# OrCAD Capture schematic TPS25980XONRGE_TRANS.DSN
size E; title: TPS25980XONRGE: 2.7- 24V, 8A, 3mOhm Smart eFuse With; rev: 1.0; note: Datasheet: NA     EVM: NA; note: Adjustable Transient Fault Management
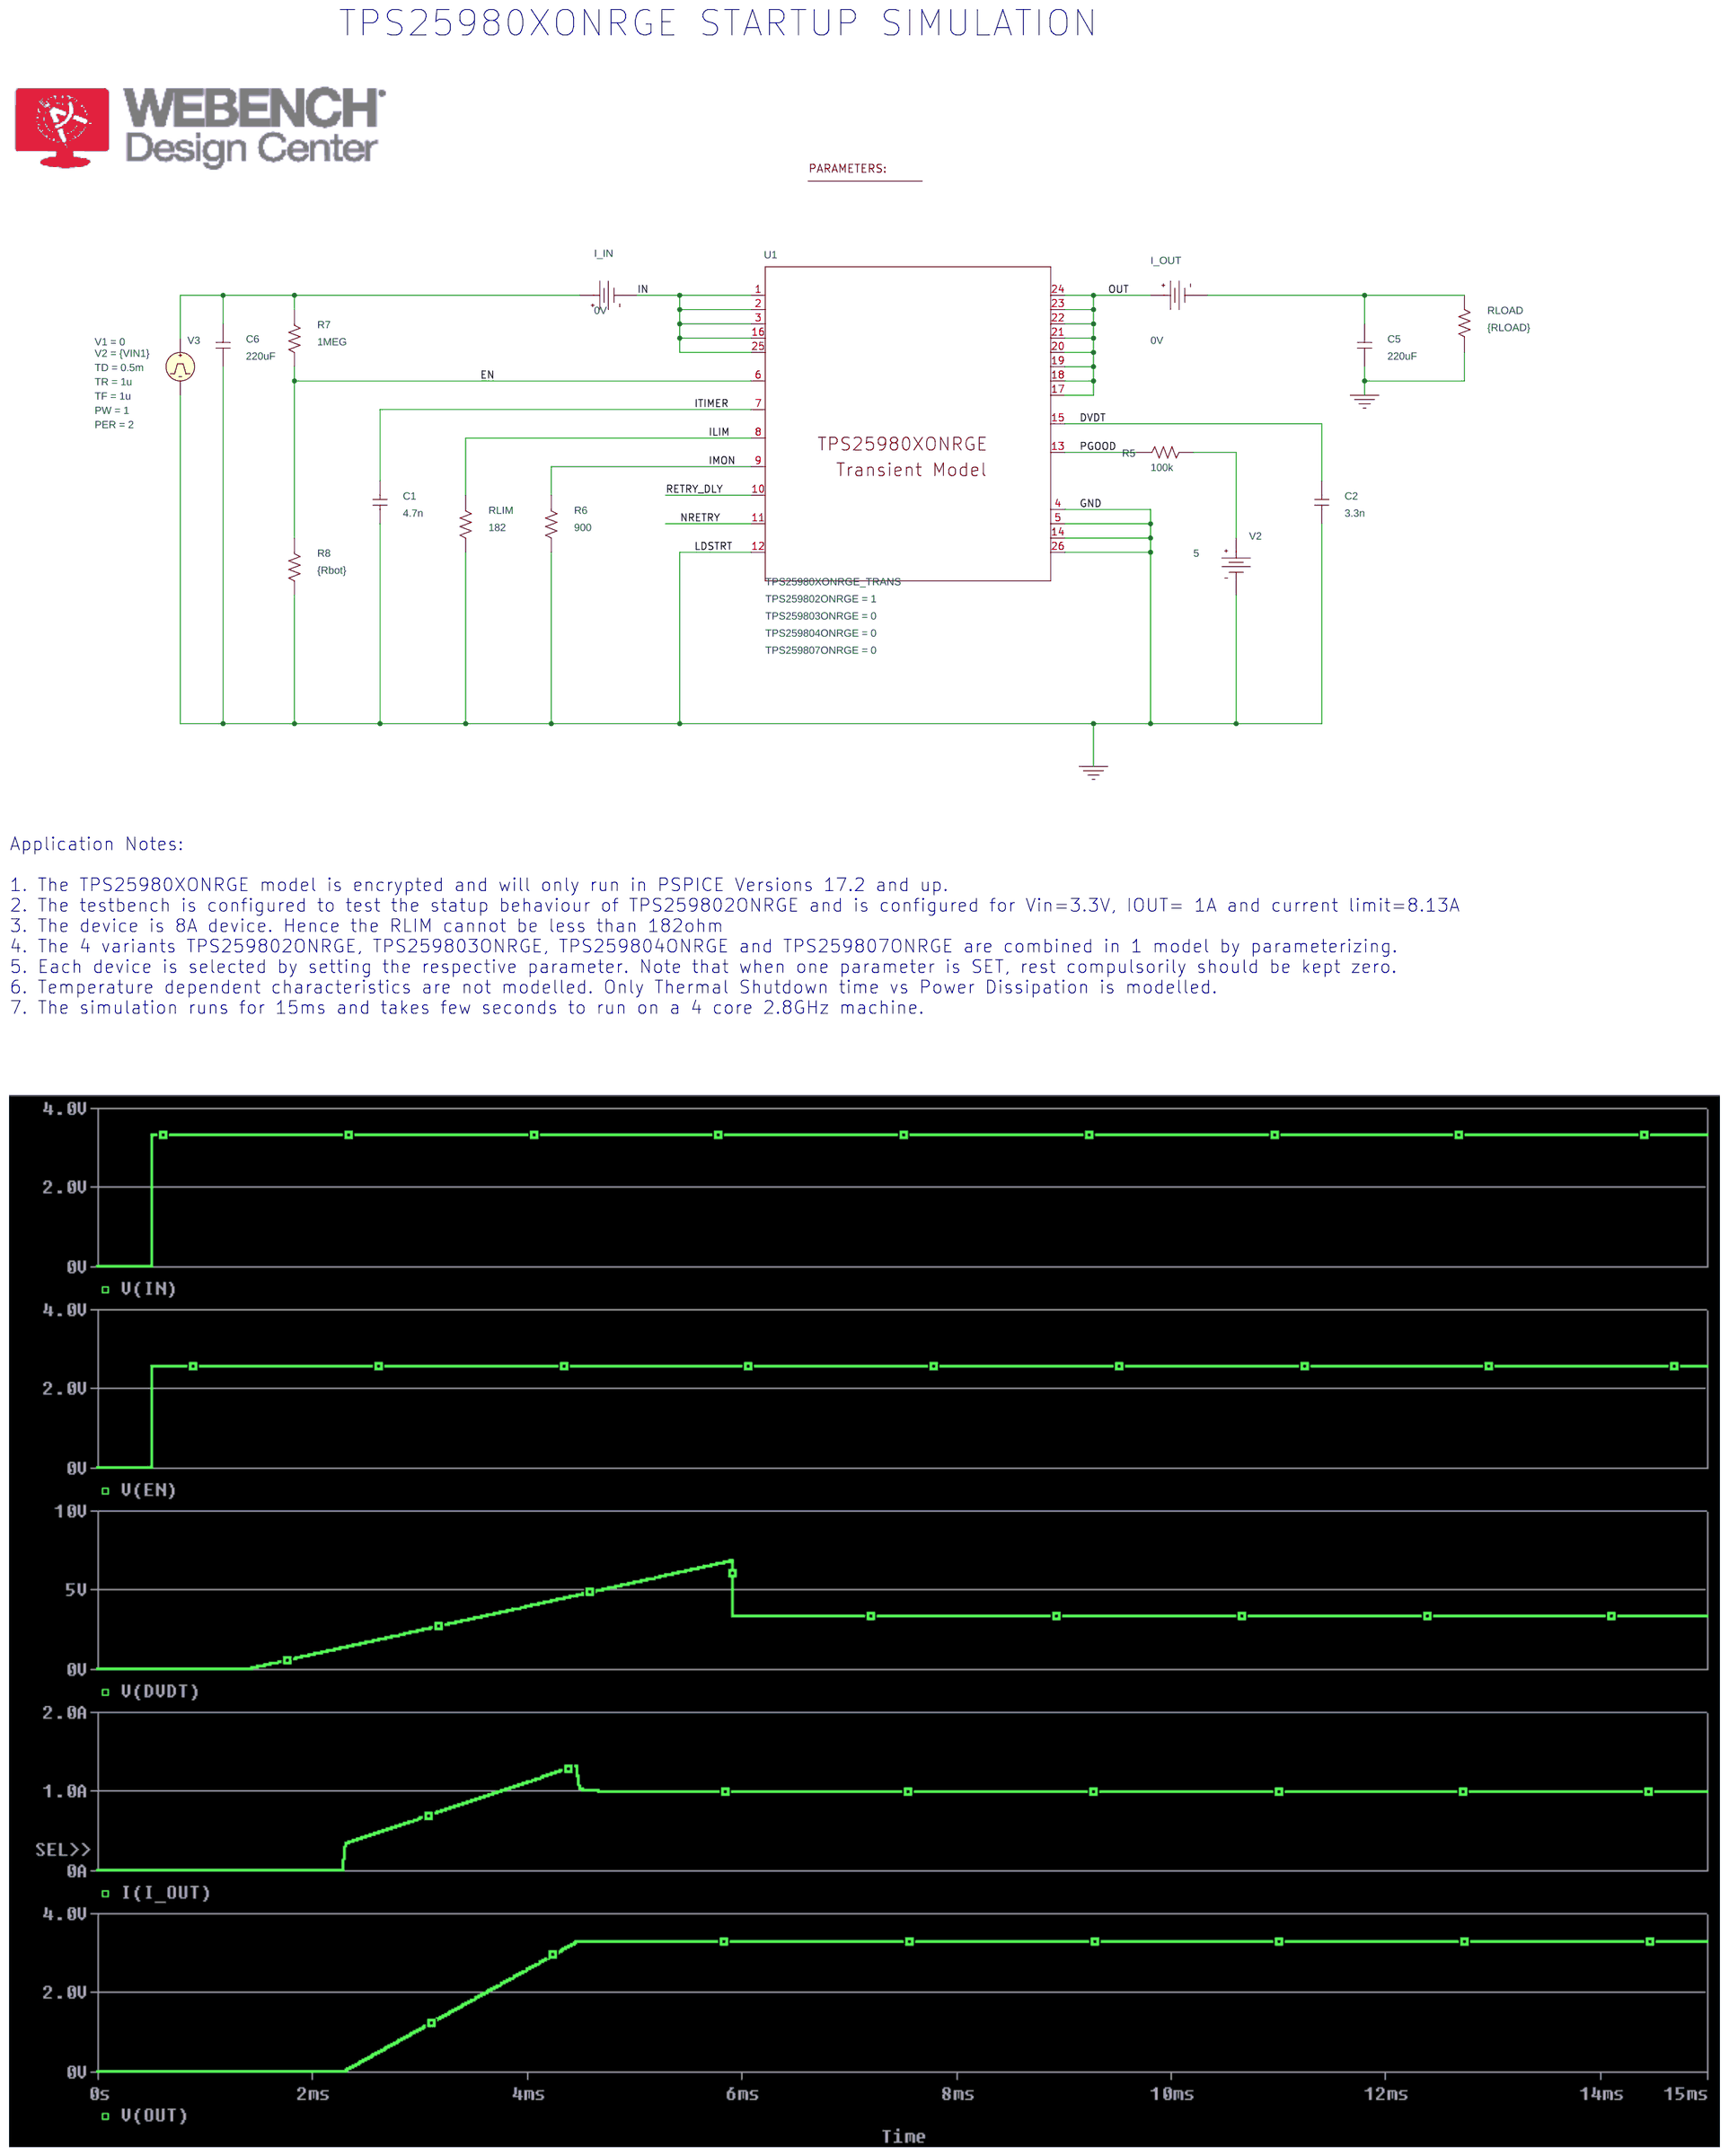
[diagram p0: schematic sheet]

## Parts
1  PARAM
C1  4.7n  [RAD/CK05]
C2  3.3n  [RAD/CK05]
C5  220uF  [RAD/CK05]
C6  220uF  [RAD/CK05]
I_IN  VDC
I_OUT  VDC
R5  100k  [AX/RC05]
R6  900  [AX/RC05]
R7  1MEG  [AX/RC05]
R8  {Rbot}  [AX/RC05]
RLIM  182  [AX/RC05]
RLOAD  {RLOAD}  [AX/RC05]
U1  TPS25980XONRGE_TRANS  [RGE0024M]
V2  VDC
V3  VPULSE

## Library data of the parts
1 = PARAM: RLOAD: 3.3; Rbot: 3.4MEG; VIN1: 3.3
C1 C2 C5 C6 = C
I_IN I_OUT = VDC: DC: 0V
R5-R8 RLIM RLOAD = R
U1 = TPS25980XONRGE_TRANS: TPS259802ONRGE: 1; TPS259803ONRGE: 0; TPS259804ONRGE: 0; TPS259807ONRGE: 0
V2 = VDC: DC: 5
V3 = VPULSE: PER: 2; PW: 1; TD: 0.5m; TF: 1u; TR: 1u; V1: 0; V2: {VIN1}

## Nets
0: C1.1 C2.1 C5.1 C6.1 R6.2 R8.2 RLIM.2 RLOAD.1 U1.4(GND_0) U1.5(GND_1) U1.12(LDSTRT) U1.14(GND_2) U1.26(GND_3) V2.1(-) V3.2(-)
DVDT: C2.2 U1.15(DVDT)
EN: R7.2 R8.1 U1.6(EN_UVLO)
ILIM: RLIM.1 U1.8(ILIM)
IMON: R6.1 U1.9(IMON)
IN: I_IN.1(-) U1.1(IN_0) U1.2(IN_1) U1.3(IN_2) U1.16(IN_3) U1.25(IN_4)
ITIMER: C1.2 U1.7(ITIMER)
NRETRY: U1.11(NRETRY)
OUT: I_OUT.0(+) U1.17(OUT_0) U1.18(OUT_1) U1.19(OUT_2) U1.20(OUT_3) U1.21(OUT_4) U1.22(OUT_5) U1.23(OUT_6) U1.24(OUT_7)
PGOOD: R5.1 U1.13(PG)
RETRY_DLY: U1.10(RETRY_DLY)
N16808169: R5.2 V2.0(+)
N16817907: C6.2 I_IN.0(+) R7.1 V3.1(+)
N16972378: C5.2 I_OUT.1(-) RLOAD.2

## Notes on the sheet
- TPS25980XONRGE STARTUP SIMULATION
- Application Notes:
  1. The TPS25980XONRGE model is encrypted and will only run in PSPICE Versions 17.2 and up.
  2. The testbench is configured to test the statup behaviour of TPS259802ONRGE and is configured for Vin=3.3V, IOUT= 1A and current limit=8.13A
  3. The device is 8A device. Hence the RLIM cannot be less than 182ohm
  4. The 4 variants TPS259802ONRGE, TPS259803ONRGE, TPS259804ONRGE and TPS259807ONRGE are combined in 1 model by parameterizing.
  5. Each device is selected by setting the respective parameter. Note that when one parameter is SET, rest compulsorily should be kept zero.
  6. Temperature dependent characteristics are not modelled. Only Thermal Shutdown time vs Power Dissipation is modelled.
  7. The simulation runs for 15ms and takes few seconds to run on a 4 core 2.8GHz machine.
